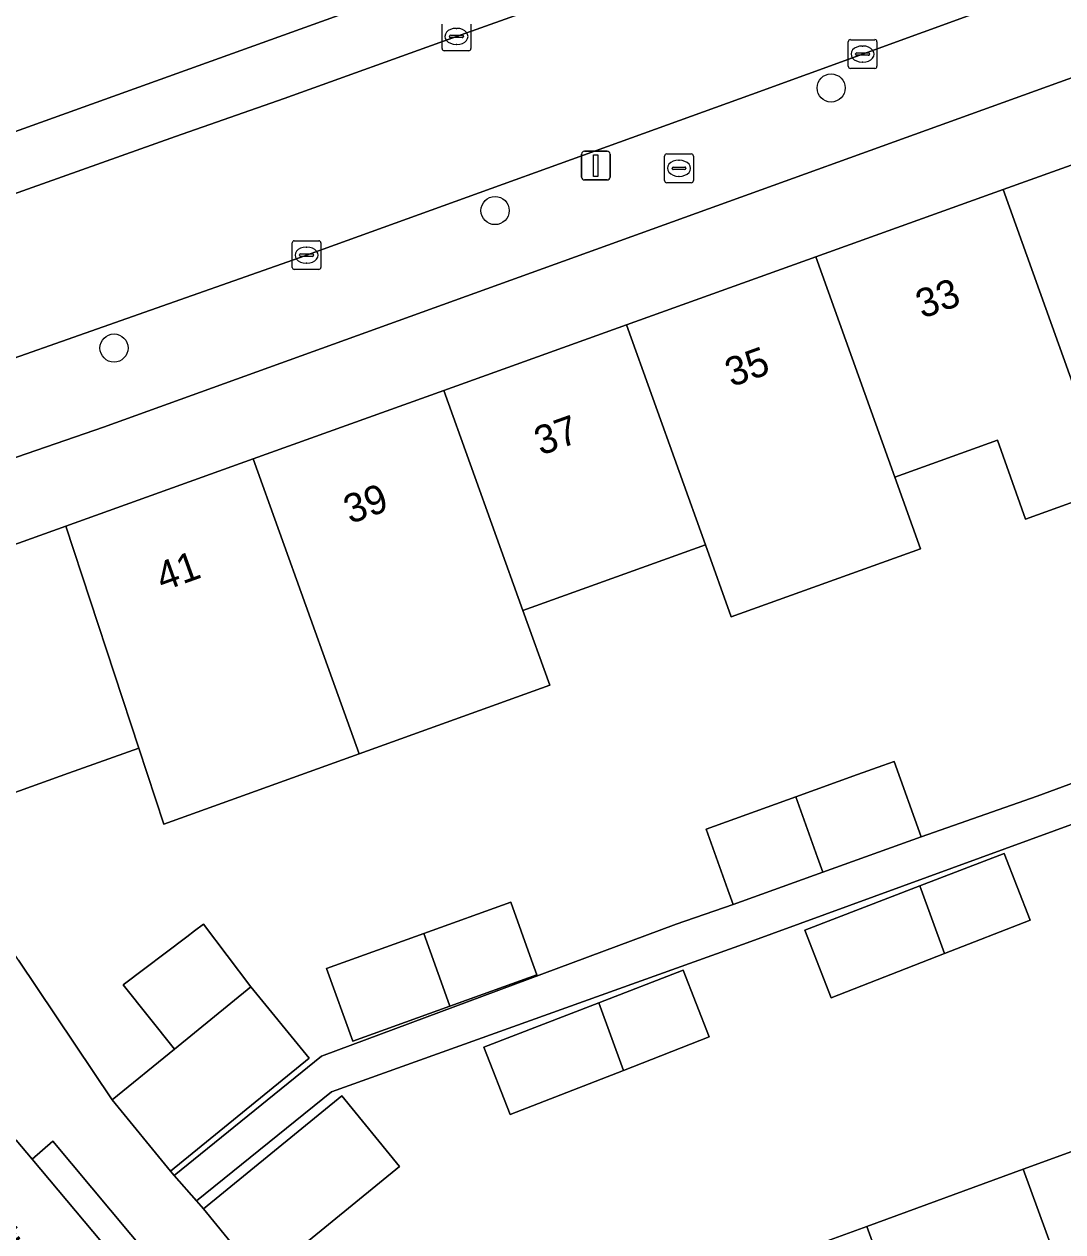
# Model space of a CAD drawing. Extents: x 162523 to 163266, y 381230 to 382050.
# Drawn here: x 162718.25 to 162754.37, y 381740.55 to 381782.56 of the extents above; entities that cross this region are included whole.
import ezdxf

# ---------------------------------------------------------------- set-up
doc = ezdxf.new("R2010")
doc.units = 0
for name, color, linetype in [('IMGEO_Boom', 7, 'Continuous'), ('IMGEO_Brandkraan', 7, 'Continuous'), ('IMGEO_Erf', 7, 'Continuous'), ('IMGEO_Kolk', 7, 'Continuous'), ('IMGEO_Lichtmast', 7, 'Continuous'), ('IMGEO_Openbare_ruimte_label', 7, 'Continuous'), ('IMGEO_Pand', 7, 'Continuous'), ('IMGEO_Pand_nummerreeks', 7, 'Continuous'), ('IMGEO_Rijbaan_lokaal_open', 7, 'Continuous'), ('IMGEO_Voetpad_open', 7, 'Continuous')]:
    doc.layers.add(name, color=color, linetype=linetype)

msp = doc.modelspace()

# ---------------------------------------------------------------- linework, layer by layer
at = {"layer": 'IMGEO_Boom'}
for centre in [(162746.312, 381780.343), (162734.625, 381776.077), (162721.375, 381771.294)]:
    msp.add_circle(centre, 0.489, dxfattribs=at)
at = {"layer": 'IMGEO_Brandkraan'}
for p, q in [((162740.596, 381778.048), (162741.448, 381778.048)), ((162740.521, 381777.122), (162740.521, 381777.974)), ((162740.823, 381777.591), (162741.221, 381777.591)), ((162741.009, 381777.828), (162741.034, 381777.828)), ((162741.522, 381777.974), (162741.522, 381777.122)), ((162740.78, 381777.542), (162740.78, 381777.554)), ((162741.218, 381777.505), (162740.82, 381777.505)), ((162741.032, 381777.268), (162741.007, 381777.268)), ((162741.264, 381777.554), (162741.264, 381777.542)), ((162741.448, 381777.048), (162740.596, 381777.048))]:
    msp.add_line(p, q, dxfattribs=at)
for points in [[(162740.596, 381778.048), (162741.448, 381778.048)], [(162740.521, 381777.122), (162740.521, 381777.974)], [(162741.522, 381777.974), (162741.522, 381777.122)], [(162741.448, 381777.048), (162740.596, 381777.048)]]:
    msp.add_lwpolyline(points, dxfattribs=at)
for centre, radius, start, end in [((162740.598, 381777.972), 0.0765, 91.552, 178.448), ((162740.598, 381777.972), 0.0765, 91.552, 178.448), ((162741.446, 381777.972), 0.0765, 1.552, 88.448), ((162741.446, 381777.972), 0.0765, 1.552, 88.448), ((162740.82, 381777.551), 0.0403, 85.8775, 175.7526), ((162741.225, 381777.553), 0.0386, 1.7309, 96.639), ((162740.817, 381777.541), 0.0366, 178.938, 274.7102), ((162741.221, 381777.548), 0.043, 264.8664, 352.4533), ((162740.598, 381777.124), 0.0765, 181.552, 268.448), ((162740.598, 381777.124), 0.0765, 181.552, 268.448), ((162741.446, 381777.124), 0.0765, 271.552, 358.448), ((162741.446, 381777.124), 0.0765, 271.552, 358.448)]:
    msp.add_arc(centre, radius, start, end, dxfattribs=at)
for centre, major_axis, ratio, start_param, end_param in [((162741.008, 381777.548), (-0.387, 0.002), 0.722429, 4.712389, 7.853982), ((162741.033, 381777.548), (-0.39, 0.002), 0.717154, 1.570796, 4.712389)]:
    msp.add_ellipse(centre, major_axis=major_axis, ratio=ratio, start_param=start_param, end_param=end_param, dxfattribs=at)
at = {"layer": 'IMGEO_Erf'}
for points in [[(162771.368, 381786.733), (162721.003, 381768.545), (162711.69, 381765.328), (162712.683, 381762.58), (162719.702, 381765.1), (162726.218, 381767.44), (162732.846, 381769.821), (162739.192, 381772.1), (162745.775, 381774.464), (162752.294, 381776.805), (162759.028, 381779.223), (162765.611, 381781.587), (162772.373, 381784.016)], [(162750.255, 381750.228), (162746.311, 381748.689), (162745.394, 381751.04), (162749.397, 381752.582), (162752.331, 381753.712), (162753.236, 381751.392)], [(162735.896, 381750.002), (162736.082, 381749.484), (162733.056, 381748.396), (162729.679, 381747.182), (162728.769, 381749.713), (162732.146, 381750.927), (162735.172, 381752.015)], [(162739.095, 381746.161), (162735.151, 381744.622), (162734.234, 381746.973), (162738.238, 381748.515), (162741.171, 381749.645), (162742.076, 381747.325)]]:
    msp.add_lwpolyline(points, close=True, dxfattribs=at)
for points in [[(162712.395, 381784.129), (162714.518, 381777.596), (162732.297, 381783.996)], [(162756.028, 381766.404), (162753.075, 381765.344), (162752.092, 381768.084), (162748.526, 381766.805), (162749.423, 381764.309), (162742.836, 381761.946), (162741.94, 381764.443), (162735.594, 381762.167), (162736.528, 381759.565), (162729.902, 381757.18), (162723.102, 381754.732), (162722.235, 381757.375), (162719.795, 381756.5), (162715.507, 381754.962)], [(162718.054, 381750), (162721.308, 381745.14), (162723.472, 381746.904), (162721.695, 381749.144), (162723.912, 381750.814), (162724.179, 381751.015), (162724.491, 381751.25), (162726.131, 381749.072), (162728.156, 381746.589), (162723.333, 381742.657), (162723.467, 381742.504), (162728.592, 381746.653), (162740.919, 381751.249), (162742.905, 381751.938), (162742.722, 381752.445), (162741.962, 381754.559), (162745.084, 381755.681), (162747.227, 381756.452), (162748.111, 381756.77), (162748.503, 381756.911), (162749.444, 381754.289), (162753.472, 381755.702), (162768.712, 381761.319)], [(162768.434, 381759.736), (162743.389, 381750.602), (162728.938, 381745.414), (162724.241, 381741.622), (162724.481, 381741.349), (162729.298, 381745.277), (162731.305, 381742.815), (162726.488, 381738.887)], [(162744.361, 381739.575), (162747.549, 381740.736), (162752.991, 381742.72), (162758.667, 381744.787)]]:
    msp.add_lwpolyline(points, dxfattribs=at)
at = {"layer": 'IMGEO_Kolk'}
for p, q in [((162732.783, 381781.711), (162732.783, 381782.563)), ((162733.271, 381782.417), (162733.296, 381782.417)), ((162733.784, 381782.563), (162733.784, 381781.711)), ((162733.042, 381782.131), (162733.042, 381782.143)), ((162733.48, 381782.094), (162733.082, 381782.094)), ((162733.085, 381782.18), (162733.483, 381782.18)), ((162733.294, 381781.857), (162733.269, 381781.857)), ((162733.526, 381782.143), (162733.526, 381782.131)), ((162746.905, 381781.097), (162746.905, 381781.949)), ((162746.98, 381782.023), (162747.832, 381782.023)), ((162747.393, 381781.803), (162747.418, 381781.803)), ((162747.906, 381781.949), (162747.906, 381781.097)), ((162733.71, 381781.637), (162732.858, 381781.637)), ((162747.164, 381781.517), (162747.164, 381781.529)), ((162747.602, 381781.48), (162747.204, 381781.48)), ((162747.207, 381781.566), (162747.605, 381781.566)), ((162747.648, 381781.529), (162747.648, 381781.517)), ((162747.832, 381781.023), (162746.98, 381781.023)), ((162747.416, 381781.243), (162747.391, 381781.243)), ((162727.569, 381774.101), (162727.569, 381774.953)), ((162727.644, 381775.027), (162728.496, 381775.027)), ((162728.057, 381774.807), (162728.082, 381774.807)), ((162728.57, 381774.953), (162728.57, 381774.101)), ((162727.828, 381774.521), (162727.828, 381774.533)), ((162728.266, 381774.484), (162727.868, 381774.484)), ((162727.871, 381774.57), (162728.269, 381774.57)), ((162728.08, 381774.247), (162728.055, 381774.247)), ((162728.312, 381774.533), (162728.312, 381774.521)), ((162728.496, 381774.027), (162727.644, 381774.027))]:
    msp.add_line(p, q, dxfattribs=at)
for points in [[(162732.783, 381781.711), (162732.783, 381782.563)], [(162733.784, 381782.563), (162733.784, 381781.711)], [(162746.905, 381781.097), (162746.905, 381781.949)], [(162746.98, 381782.023), (162747.832, 381782.023)], [(162747.906, 381781.949), (162747.906, 381781.097)], [(162733.71, 381781.637), (162732.858, 381781.637)], [(162747.832, 381781.023), (162746.98, 381781.023)], [(162727.569, 381774.101), (162727.569, 381774.953)], [(162727.644, 381775.027), (162728.496, 381775.027)], [(162728.57, 381774.953), (162728.57, 381774.101)], [(162728.496, 381774.027), (162727.644, 381774.027)]]:
    msp.add_lwpolyline(points, dxfattribs=at)
for centre, radius, start, end in [((162733.082, 381782.14), 0.0403, 85.8775, 175.7526), ((162733.079, 381782.13), 0.0366, 178.938, 274.7102), ((162733.483, 381782.137), 0.043, 264.8664, 352.4533), ((162733.487, 381782.142), 0.0386, 1.7309, 96.639), ((162746.982, 381781.947), 0.0765, 91.552, 178.448), ((162746.982, 381781.947), 0.0765, 91.552, 178.448), ((162747.83, 381781.947), 0.0765, 1.552, 88.448), ((162747.83, 381781.947), 0.0765, 1.552, 88.448), ((162732.86, 381781.713), 0.0765, 181.552, 268.448), ((162732.86, 381781.713), 0.0765, 181.552, 268.448), ((162733.708, 381781.713), 0.0765, 271.552, 358.448), ((162733.708, 381781.713), 0.0765, 271.552, 358.448), ((162747.204, 381781.526), 0.0403, 85.8775, 175.7526), ((162747.201, 381781.516), 0.0366, 178.938, 274.7102), ((162747.605, 381781.523), 0.043, 264.8664, 352.4533), ((162747.609, 381781.528), 0.0386, 1.7309, 96.639), ((162746.982, 381781.099), 0.0765, 181.552, 268.448), ((162746.982, 381781.099), 0.0765, 181.552, 268.448), ((162747.83, 381781.099), 0.0765, 271.552, 358.448), ((162747.83, 381781.099), 0.0765, 271.552, 358.448), ((162727.646, 381774.951), 0.0765, 91.552, 178.448), ((162727.646, 381774.951), 0.0765, 91.552, 178.448), ((162728.494, 381774.951), 0.0765, 1.552, 88.448), ((162728.494, 381774.951), 0.0765, 1.552, 88.448), ((162727.868, 381774.53), 0.0403, 85.8775, 175.7526), ((162727.865, 381774.52), 0.0366, 178.938, 274.7102), ((162728.269, 381774.527), 0.043, 264.8664, 352.4533), ((162728.273, 381774.532), 0.0386, 1.7309, 96.639), ((162727.646, 381774.103), 0.0765, 181.552, 268.448), ((162727.646, 381774.103), 0.0765, 181.552, 268.448), ((162728.494, 381774.103), 0.0765, 271.552, 358.448), ((162728.494, 381774.103), 0.0765, 271.552, 358.448)]:
    msp.add_arc(centre, radius, start, end, dxfattribs=at)
for centre, major_axis, ratio, start_param, end_param in [((162733.27, 381782.137), (-0.387, 0.002), 0.722429, 4.712389, 7.853982), ((162733.295, 381782.137), (-0.39, 0.002), 0.717154, 1.570796, 4.712389), ((162747.392, 381781.523), (-0.387, 0.002), 0.722429, 4.712389, 7.853982), ((162747.417, 381781.523), (-0.39, 0.002), 0.717154, 1.570796, 4.712389), ((162728.056, 381774.527), (-0.387, 0.002), 0.722429, 4.712389, 7.853982), ((162728.081, 381774.527), (-0.39, 0.002), 0.717154, 1.570796, 4.712389)]:
    msp.add_ellipse(centre, major_axis=major_axis, ratio=ratio, start_param=start_param, end_param=end_param, dxfattribs=at)
at = {"layer": 'IMGEO_Lichtmast'}
for p, q in [((162737.633, 381777.243), (162737.633, 381778.043)), ((162737.633, 381778.043), (162737.633, 381777.243)), ((162737.733, 381778.143), (162738.523, 381778.143)), ((162738.523, 381778.143), (162737.733, 381778.143)), ((162738.623, 381778.043), (162738.623, 381777.243)), ((162738.623, 381777.243), (162738.623, 381778.043)), ((162738.523, 381777.143), (162737.733, 381777.143)), ((162737.733, 381777.143), (162738.523, 381777.143))]:
    msp.add_line(p, q, dxfattribs=at)
msp.add_lwpolyline([(162738.053, 381778.018), (162738.203, 381778.018), (162738.203, 381777.268), (162738.053, 381777.268), (162738.053, 381778.018)], dxfattribs=at)
for centre, start, end in [((162737.733, 381778.043), 90, 180), ((162737.733, 381778.043), 90, 180), ((162738.523, 381778.043), 0, 90), ((162738.523, 381778.043), 360, 90), ((162737.733, 381777.243), 180, 270), ((162737.733, 381777.243), 180, 270), ((162738.523, 381777.243), 270, 0), ((162738.523, 381777.243), 270, 0)]:
    msp.add_arc(centre, 0.1, start, end, dxfattribs=at)
at = {"layer": 'IMGEO_Pand'}
for points in [[(162755.045, 381769.143), (162761.78, 381771.559), (162759.028, 381779.223), (162752.294, 381776.805)], [(162752.294, 381776.805), (162745.775, 381774.464), (162748.526, 381766.805), (162752.092, 381768.084), (162753.075, 381765.344), (162756.028, 381766.404), (162755.045, 381769.143)], [(162745.775, 381774.464), (162739.192, 381772.1), (162741.94, 381764.443), (162742.836, 381761.946), (162749.423, 381764.309), (162748.526, 381766.805)], [(162735.594, 381762.167), (162741.94, 381764.443), (162739.192, 381772.1), (162732.846, 381769.821)], [(162735.594, 381762.167), (162732.846, 381769.821), (162726.218, 381767.44), (162728.965, 381759.789), (162729.902, 381757.18), (162736.528, 381759.565)], [(162726.218, 381767.44), (162719.702, 381765.1), (162722.235, 381757.375), (162723.102, 381754.732), (162729.902, 381757.18), (162728.965, 381759.789)], [(162722.235, 381757.375), (162719.702, 381765.1), (162712.683, 381762.58), (162712.302, 381762.443), (162712.433, 381762.08), (162712.806, 381762.214), (162715.287, 381755.295), (162714.957, 381755.177), (162715.088, 381754.812), (162715.507, 381754.962), (162719.795, 381756.5)], [(162745.084, 381755.681), (162745.843, 381753.567), (162746.025, 381753.06), (162749.444, 381754.289), (162748.503, 381756.911), (162748.111, 381756.77), (162747.227, 381756.452)], [(162745.084, 381755.681), (162741.962, 381754.559), (162742.722, 381752.445), (162742.905, 381751.938), (162746.025, 381753.06), (162745.843, 381753.567)], [(162750.255, 381750.228), (162753.236, 381751.392), (162752.331, 381753.712), (162749.397, 381752.582)], [(162750.255, 381750.228), (162749.397, 381752.582), (162745.394, 381751.04), (162746.311, 381748.689)], [(162735.172, 381752.015), (162732.146, 381750.927), (162732.87, 381748.914), (162733.056, 381748.396), (162736.082, 381749.484), (162735.896, 381750.002)], [(162726.131, 381749.072), (162724.491, 381751.25), (162724.179, 381751.015), (162723.912, 381750.814), (162721.695, 381749.144), (162723.472, 381746.904)], [(162732.146, 381750.927), (162728.769, 381749.713), (162729.679, 381747.182), (162733.056, 381748.396), (162732.87, 381748.914)], [(162739.095, 381746.161), (162742.076, 381747.325), (162741.171, 381749.645), (162738.238, 381748.515)], [(162728.156, 381746.589), (162726.131, 381749.072), (162723.472, 381746.904), (162721.308, 381745.14), (162723.333, 381742.657)], [(162739.095, 381746.161), (162738.238, 381748.515), (162734.234, 381746.973), (162735.151, 381744.622)], [(162731.305, 381742.815), (162729.298, 381745.277), (162724.481, 381741.349), (162726.488, 381738.887)], [(162752.991, 381742.72), (162754.539, 381738.472), (162753.211, 381737.988), (162754.777, 381733.689), (162760.453, 381735.756), (162758.887, 381740.055), (162760.215, 381740.539), (162758.667, 381744.787)], [(162747.549, 381740.736), (162749.096, 381736.49), (162747.768, 381736.006), (162749.334, 381731.706), (162754.777, 381733.689), (162753.211, 381737.988), (162754.539, 381738.472), (162752.991, 381742.72)], [(162747.549, 381740.736), (162744.361, 381739.575), (162741.831, 381738.653), (162743.378, 381734.407), (162742.05, 381733.923), (162743.616, 381729.624), (162749.334, 381731.706), (162747.768, 381736.006), (162749.096, 381736.49)]]:
    msp.add_lwpolyline(points, close=True, dxfattribs=at)
at = {"layer": 'IMGEO_Rijbaan_lokaal_open'}
for points in [[(162810.992, 381807.398), (162807.475, 381806.37), (162804.287, 381805.438), (162800.354, 381804.283), (162796.87, 381803.259), (162787.905, 381800.573), (162778.822, 381797.969), (162772.588, 381796.113), (162768.08, 381794.68), (162761.762, 381792.555), (162754.947, 381789.947), (162750.568, 381788.41), (162740.129, 381784.59), (162736.996, 381783.467), (162733.281, 381782.136), (162727.293, 381779.975), (162723.508, 381778.659), (162709.271, 381773.592), (162698.385, 381769.691), (162695.37, 381768.61), (162703.464, 381763.466)], [(162705.951, 381766.584), (162710.603, 381768.297), (162715.816, 381770.216), (162727.812, 381774.435), (162743.537, 381780.118), (162755.484, 381784.46), (162766.727, 381788.461), (162769.038, 381789.246), (162772.813, 381790.449), (162776.799, 381791.68), (162781.286, 381793.023), (162787.489, 381794.819), (162796.363, 381797.487)], [(162702.219, 381756.423), (162707.598, 381750), (162709.828, 381747.338), (162714.157, 381742.181), (162716.593, 381739.279), (162716.915, 381738.896), (162725.543, 381728.658), (162725.961, 381728.158), (162730.346, 381722.768), (162731.08, 381721.865), (162731.988, 381720.709), (162735.076, 381723.106), (162734.001, 381724.355), (162727.299, 381732.493), (162724.189, 381736.27), (162721.8, 381739.172), (162720.936, 381740.202), (162718.528, 381743.072), (162717.972, 381743.735), (162712.715, 381750), (162705.833, 381757.992)]]:
    msp.add_lwpolyline(points, dxfattribs=at)
at = {"layer": 'IMGEO_Voetpad_open'}
for points in [[(162819.812, 381804.396), (162808.82, 381801.17), (162802.377, 381799.307), (162796.363, 381797.487), (162787.489, 381794.819), (162781.286, 381793.023), (162776.799, 381791.68), (162772.813, 381790.449), (162769.038, 381789.246), (162766.727, 381788.461), (162755.484, 381784.46), (162743.537, 381780.118), (162727.812, 381774.435), (162715.816, 381770.216), (162710.603, 381768.297), (162711.69, 381765.328), (162721.003, 381768.545), (162771.368, 381786.733), (162772.373, 381784.016), (162772.781, 381784.162), (162774.9, 381784.789), (162775.329, 381784.916), (162774.54, 381787.759), (162837.328, 381806.26)], [(162723.508, 381778.659), (162727.293, 381779.975), (162733.281, 381782.136), (162736.996, 381783.467), (162734.076, 381787.564)], [(162732.297, 381783.996), (162714.518, 381777.596), (162713.049, 381777.067), (162699.372, 381772.144), (162699.337, 381772.114), (162699.326, 381772.127), (162696.883, 381771.248), (162698.385, 381769.691), (162709.271, 381773.592), (162723.508, 381778.659)], [(162726.488, 381738.887), (162724.481, 381741.349), (162724.241, 381741.622), (162723.467, 381742.504), (162723.333, 381742.657), (162721.308, 381745.14), (162718.054, 381750), (162716.34, 381752.561), (162715.507, 381754.962), (162715.088, 381754.812), (162714.957, 381755.177), (162715.287, 381755.295), (162712.806, 381762.214)], [(162768.712, 381761.319), (162753.472, 381755.702), (162749.444, 381754.289), (162746.025, 381753.06), (162742.905, 381751.938), (162740.919, 381751.249), (162728.592, 381746.653), (162723.467, 381742.504), (162724.241, 381741.622), (162728.938, 381745.414), (162743.389, 381750.602), (162768.434, 381759.736)], [(162717.972, 381743.735), (162718.528, 381743.072), (162719.251, 381743.697), (162728.038, 381733.186)]]:
    msp.add_lwpolyline(points, dxfattribs=at)
msp.add_lwpolyline([(162718.528, 381743.072), (162720.936, 381740.202), (162721.8, 381739.172), (162724.189, 381736.27), (162727.299, 381732.493), (162728.038, 381733.186), (162719.251, 381743.697)], close=True, dxfattribs=at)

# ---------------------------------------------------------------- texts
at = {"layer": 'IMGEO_Openbare_ruimte_label'}
msp.add_text('St Gertrudislaan', height=1, rotation=310.0917, dxfattribs=at).set_placement((162714.682, 381743.216))
at = {"layer": 'IMGEO_Pand_nummerreeks'}
for s, rotation, p in [('33', 19.7556, (162749.481, 381772.309)), ('35', 19.7556, (162742.849, 381769.928)), ('37', 19.754, (162736.217, 381767.546)), ('39', 19.754, (162729.585, 381765.165)), ('41', 19.7556, (162723.061, 381762.821))]:
    msp.add_text(s, height=1, rotation=rotation, dxfattribs=at).set_placement(p)

doc.saveas('drawing.dxf')
